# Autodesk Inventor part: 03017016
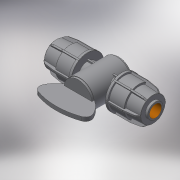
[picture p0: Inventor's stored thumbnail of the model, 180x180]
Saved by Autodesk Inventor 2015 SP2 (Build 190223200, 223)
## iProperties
Created: 2017-05
Part Number: 03017016
Material: Generic
Description: PLASSON 1/4 TURN VALVE COMPRESSION X COMPRESSION 16X16
Document SubType Name: Modeling
Designer: KIM
Mass: 68.7518 g
Surface Area: 219.87 cm^2
Volume: 68.7518 cm^3
Density: 1 g/cm^3
Appearance: Default
Author: KIM
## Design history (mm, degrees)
derived "03017.ipt"
feature "Solid1::03017.ipt"
tag "TaggingFeature1"
body "Solid1"
other parameters: "d0" = 105, "d3" = 16, "d4" = 12.59228, "d5" = 16, "d6" = 34, "d8" = 17, "d9" = 35, "d10" = 2.625, "d11" = 30.6, "d12" = 27.2, "d13" = 25.5, "d14" = 2.625, "d15" = 19.2, "d19" = 0.245, "d25" = 1.47, "d26" = 0, "d27" = 4.9, "d29" = 360 deg, "d31" = 49, "d32" = 1.05, "d33" = 18.7, "d34" = 24.5, "d36" = 14.96, "d38" = 2.45, "d39" = 22.4, "d40" = 1.47, "d41" = 0, "d43" = 360 deg, "d45" = 49, "d46" = 52, "d47" = 45, "d48" = 4, "d49" = 0, "d50" = 29, "d51" = 2, "d52" = 0, "d53" = 8, "d59" = 40 deg, "d60" = 25.5, "d62" = 3.2375, "d64" = 0, "L_" = 105, "A_" = 49, "E_" = 34, "l_" = 17, "d_" = 16, "d61" = 32.375
